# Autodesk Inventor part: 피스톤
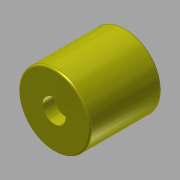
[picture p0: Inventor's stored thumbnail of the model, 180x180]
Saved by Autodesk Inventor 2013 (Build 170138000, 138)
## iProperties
Created: 2018-01
Part Number: 피스톤
Material: 강철, 탄소
Document SubType Name: Modeling
Designer: mduedu
Density: 1 g/cm^3
Author: mduedu
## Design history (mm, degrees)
sketch "스케치1"
  geometry: C1 r 10 at (0, 0); 1 further point
  constraints: 1 centre point, 1 coincident
  dimensions: "d0" = 20 diameter of C1
extrude "돌출1" new body sketch "스케치1" distance "d1" = 20; taper "d2" = 0 deg
hole "구멍1" diameter "d5" = 7; stored, may be unused: countersink angle "d9" = 90 deg, drill point angle "d11" = 0 deg; dims "d6" = 6, "d7" = 4, "d8" = 2, "d10" = 10, "d12" = 10, "d13" = 10
chamfer "모따기1" distance "d14" = 0.5; stored, may be unused: second distance "d15" = 2, angle "d16" = 45 deg
fillet "모깎기1" dims "d17" = 0.5
sketch "스케치2"
  geometry: 2 further points
  constraints: 1 coincident
sketch "스케치3"
  geometry: 2 further points
  constraints: 1 coincident
hole "구멍2" sketch "스케치3" at (0, 0) diameter "d18" = 3.4; stored, may be unused: countersink angle "d22" = 90 deg, drill point angle "d24" = 0 deg; dims "d19" = 6, "d20" = 6.5, "d21" = 3.4, "d23" = 8
node "솔리드1"
